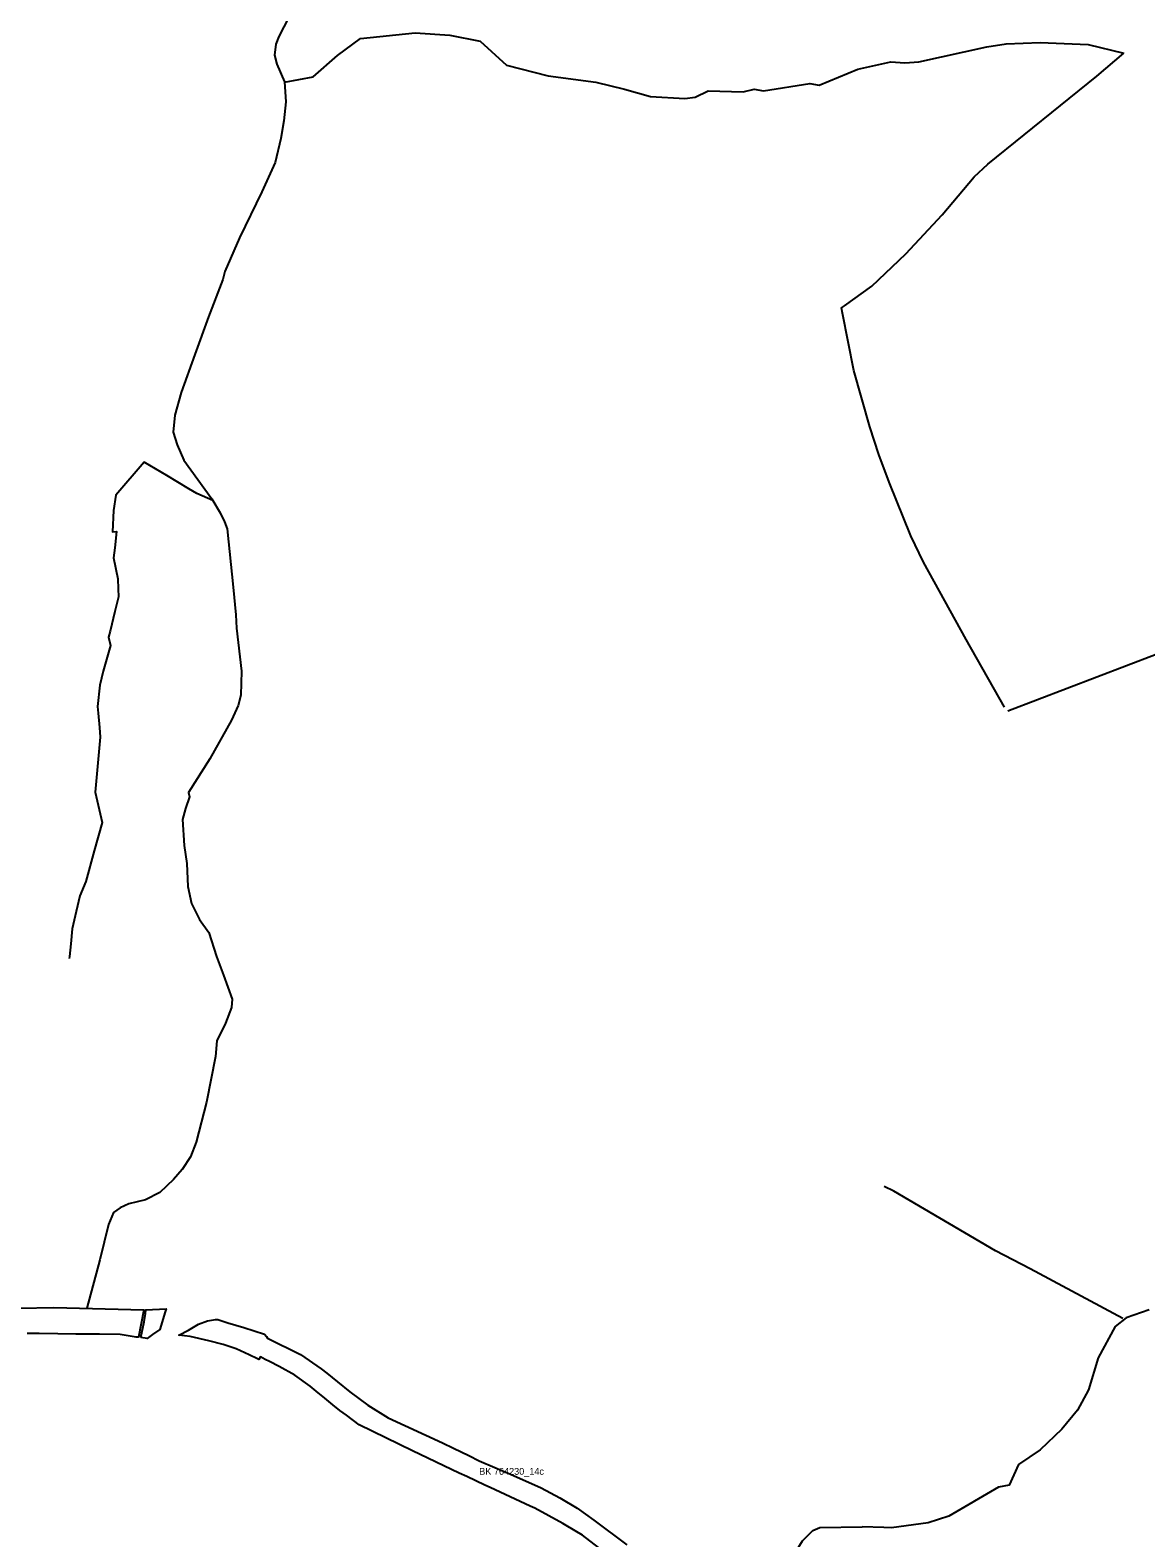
# Model space of a CAD drawing. Extents: x -521616 to -516782, y -1190061 to -1184927.
# Drawn here: x -519047 to -517900, y -1187423 to -1185873 of the extents above; entities that cross this region are included whole.
import ezdxf

# ---------------------------------------------------------------- set-up
doc = ezdxf.new("R2010")
doc.units = 0
for name, color, linetype in [('i_prvek_l_n', 7, 'Continuous'), ('i_prvek_l_s', 7, 'Continuous'), ('LBK_s', 7, 'Continuous')]:
    doc.layers.add(name, color=color, linetype=linetype)

msp = doc.modelspace()

# ---------------------------------------------------------------- linework, layer by layer
at = {"layer": 'i_prvek_l_n'}
for points in [[(-518045, -1186568.8), (-518084.4, -1186499.5), (-518128.4, -1186419.7), (-518141.4, -1186392.7), (-518163.7, -1186337.6), (-518174.3, -1186309), (-518183.5, -1186280.5), (-518199.9, -1186222.5), (-518211.5, -1186163.6), (-518212.7, -1186158.1), (-518209.5, -1186156.1), (-518181.5, -1186135.9), (-518146.4, -1186102.7), (-518109, -1186062.4), (-518076.2, -1186023.4), (-518062.1, -1186010.5), (-517950.1, -1185919.7), (-517922.3, -1185896.1)], [(-518327.8, -1187548.3), (-518252.9, -1187426.5), (-518242, -1187415.8), (-518235, -1187412.9), (-518191.3, -1187412)]]:
    msp.add_lwpolyline(points, dxfattribs=at)
at = {"layer": 'i_prvek_l_s'}
for points in [[(-518770.5, -1185838.3), (-518791.4, -1185879.2), (-518794.5, -1185886.9), (-518796, -1185898.4), (-518793.4, -1185907.6), (-518785.5, -1185925.6), (-518784.2, -1185946.2), (-518786.3, -1185965.8), (-518789.3, -1185983.9), (-518795.3, -1186008.6), (-518808.8, -1186038.9), (-518831.7, -1186086.1), (-518847.1, -1186120.8), (-518848.9, -1186129.1), (-518863.9, -1186167.3), (-518877.8, -1186206.3), (-518891.9, -1186245.3), (-518898.4, -1186268.6), (-518900, -1186285.9), (-518896, -1186299.2), (-518889, -1186315), (-518860.4, -1186354.5), (-518851.7, -1186369.2), (-518847.2, -1186378.4), (-518844.6, -1186385.4), (-518838.2, -1186445.5), (-518835.6, -1186474), (-518834.8, -1186487.6), (-518829.9, -1186532.1), (-518830.5, -1186556.5), (-518833.1, -1186567.1), (-518840, -1186582.5), (-518862.5, -1186622.2), (-518884.2, -1186656.9), (-518883.2, -1186661.2), (-518887.5, -1186673.2), (-518890.4, -1186684.5), (-518888.6, -1186711.4), (-518885.9, -1186729.7), (-518884.9, -1186753.4), (-518881.3, -1186771), (-518873.1, -1186787.4), (-518863.5, -1186800.9), (-518855.4, -1186825.3), (-518848.4, -1186844.8), (-518839.5, -1186869.2), (-518840, -1186878), (-518846.2, -1186893.9), (-518855.3, -1186912.1), (-518856.5, -1186928.3), (-518865.9, -1186975.2), (-518876.4, -1187016.4), (-518882.3, -1187031.4), (-518890.9, -1187044.7), (-518899.6, -1187054.9), (-518913.8, -1187068.2), (-518928.7, -1187075.7), (-518945.6, -1187079.9), (-518954.7, -1187084), (-518961.4, -1187088.8), (-518966.6, -1187101.1), (-518975.6, -1187137.4), (-518989, -1187187.3)], [(-518785.5, -1185925.9), (-518756.2, -1185920.6), (-518731.2, -1185898.6), (-518707.3, -1185881.2), (-518651.1, -1185875.4), (-518615.6, -1185877.8), (-518584.4, -1185884), (-518557.2, -1185908.5), (-518514.5, -1185919.6), (-518465.2, -1185926.1), (-518435.9, -1185933.1), (-518409.2, -1185940.6), (-518373.7, -1185942.7), (-518363.1, -1185941.4), (-518349.7, -1185935), (-518313.7, -1185936.1), (-518302.5, -1185933.3), (-518292.8, -1185935), (-518245.2, -1185927.5), (-518235.7, -1185929.2), (-518195.8, -1185912.8), (-518162, -1185905), (-518147.4, -1185906.2), (-518133.1, -1185905), (-518063.2, -1185889.7), (-518043.4, -1185886.5), (-518008.5, -1185885.1), (-517959.1, -1185887.2), (-517922.3, -1185896.1)], [(-518041.6, -1186572.7), (-517888.9, -1186514.4), (-517779.9, -1186466.6), (-517714.7, -1186413.9), (-517685.2, -1186383.8), (-517659.5, -1186362), (-517653.4, -1186355.5), (-517625.7, -1186334.2), (-517600.9, -1186315.4), (-517567.3, -1186288.9)], [(-518859.3, -1186356.3), (-518875.8, -1186349.3), (-518883.8, -1186344.5), (-518906.6, -1186330.5), (-518929.8, -1186317.1), (-518959.2, -1186350.8), (-518961.6, -1186366.5), (-518962.5, -1186388.6), (-518958.4, -1186388.1), (-518960.2, -1186405.1), (-518961.4, -1186415.5), (-518957.1, -1186437.1), (-518956.6, -1186447.2), (-518956.3, -1186455.3), (-518960.1, -1186470.7), (-518965, -1186490.7), (-518966.6, -1186497.1), (-518964.7, -1186505.4), (-518972, -1186531.8), (-518975.5, -1186546.2), (-518977.8, -1186568.4), (-518977.2, -1186575), (-518975.9, -1186589.8), (-518975, -1186599.9), (-518980.2, -1186656.5), (-518973.1, -1186687.6), (-518981.4, -1186716.6), (-518989.9, -1186748.3), (-518996.1, -1186763.1), (-518999.8, -1186779), (-519004, -1186797.1), (-519005.4, -1186812.4), (-519006.7, -1186825.4), (-519006.9, -1186827.5)], [(-517923.2, -1187197.9), (-518018.5, -1187146.7), (-518054.2, -1187128.2), (-518158.8, -1187066.8), (-518168.7, -1187062.2)], [(-517896.4, -1187189.1), (-517919.8, -1187197.1), (-517931.2, -1187206), (-517948.6, -1187238.3), (-517958.6, -1187271.3), (-517970, -1187292), (-517985.9, -1187311.7), (-518008.2, -1187333.1), (-518030.8, -1187347.9), (-518040.3, -1187369.3), (-518051.1, -1187371.3), (-518102.4, -1187401.3), (-518123.7, -1187408), (-518161.4, -1187413.1), (-518169, -1187412.9), (-518191.3, -1187412)]]:
    msp.add_lwpolyline(points, dxfattribs=at)
at = {"layer": 'LBK_s'}
for points in [[(-519058.1, -1187187.2), (-519022.8, -1187186.4), (-518930.1, -1187188.9), (-518935.7, -1187217.2), (-518938.1, -1187216.9), (-518954.5, -1187214.2), (-518975.7, -1187213.9), (-518979.7, -1187213.9), (-518997.6, -1187213.8), (-519000.3, -1187213.8), (-519018.8, -1187213.7), (-519037.8, -1187213.2), (-519050.3, -1187213.3)], [(-518462.6, -1187433.3), (-518479, -1187420.8), (-518495.8, -1187410.8), (-518499.2, -1187408.9), (-518528.1, -1187392.9), (-518532.8, -1187390.9), (-518574.2, -1187371.7), (-518579.5, -1187369.3), (-518597.9, -1187360.5), (-518605.8, -1187356.8), (-518654, -1187334), (-518708.7, -1187307.1), (-518721.8, -1187297.4), (-518728.6, -1187292.4), (-518735.7, -1187286.8), (-518744.2, -1187279.7), (-518752.9, -1187272.7), (-518759.3, -1187267.6), (-518775, -1187256.3), (-518791.1, -1187247.4), (-518801.1, -1187242.1), (-518805.4, -1187239.9), (-518810.4, -1187237.2), (-518812, -1187240.1), (-518813.4, -1187239.4), (-518822, -1187235.1), (-518835.4, -1187228.9), (-518848.8, -1187224.7), (-518863.3, -1187220.8), (-518882.5, -1187216.4), (-518894.3, -1187215), (-518884.4, -1187209.7), (-518874.1, -1187203.6), (-518864.6, -1187200.3), (-518856.6, -1187199), (-518854.2, -1187198.9), (-518843.8, -1187202.3), (-518827.5, -1187207.1), (-518806.1, -1187213.9), (-518804.2, -1187216.4), (-518802.9, -1187218), (-518769.2, -1187234.8), (-518747.8, -1187249.5), (-518741.9, -1187254.2), (-518731.1, -1187262.9), (-518718.5, -1187273.4), (-518699.8, -1187287), (-518678.9, -1187300), (-518623.2, -1187325.6), (-518611.7, -1187331.2), (-518596.1, -1187338.9), (-518585.5, -1187344.1), (-518553.1, -1187357.9), (-518521.6, -1187372.1), (-518502.5, -1187382.2), (-518484.7, -1187392.9), (-518467.3, -1187405.3), (-518433.5, -1187430.6)]]:
    msp.add_lwpolyline(points, dxfattribs=at)
msp.add_lwpolyline([(-518933.2, -1187217.5), (-518929.9, -1187201.2), (-518928.7, -1187192.6), (-518928.1, -1187188.9), (-518907.3, -1187187.8), (-518907.6, -1187188.8), (-518907.9, -1187189.9), (-518908.2, -1187191), (-518913.9, -1187209.3), (-518921.2, -1187214.4), (-518926.9, -1187218.3)], close=True, dxfattribs=at)

# ---------------------------------------------------------------- texts
msp.add_text('BK 764230_14c', height=7, dxfattribs=at).set_placement((-518585.3, -1187358.6))

doc.saveas('drawing.dxf')
